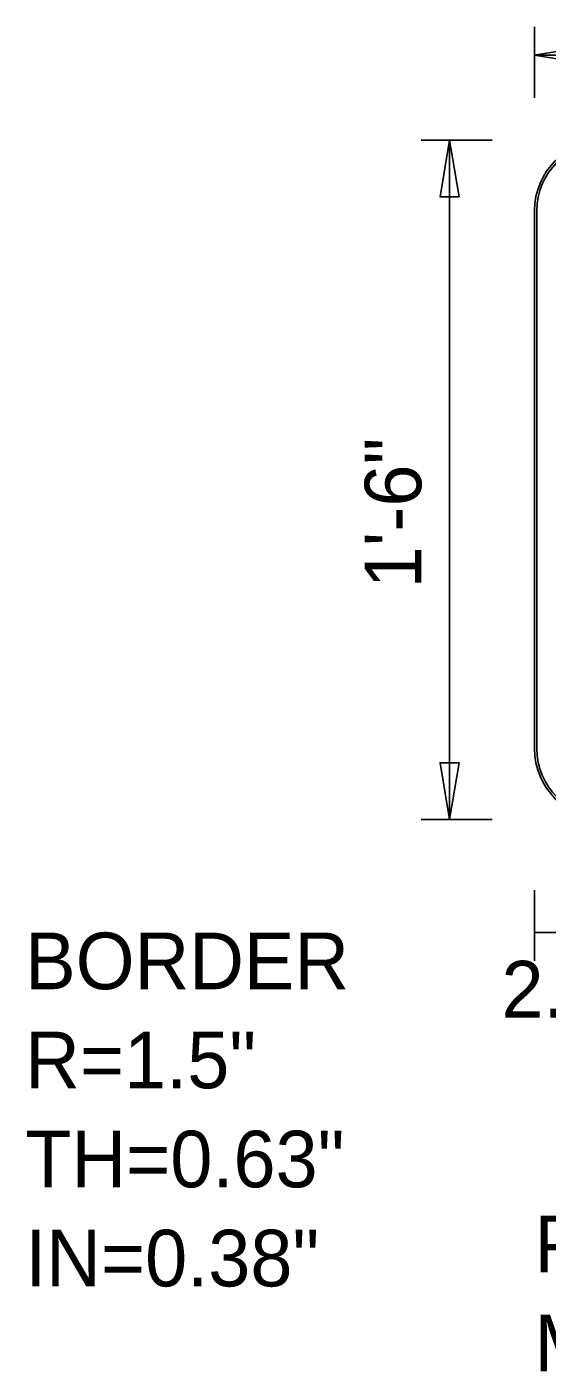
# Model space of a CAD drawing. Extents: x 1788.1 to 1851.2, y 237.2 to 283.4.
# Drawn here: x 1837.493 to 1838.871, y 249.203 to 252.768 of the extents above; entities that cross this region are included whole.
import ezdxf

# ---------------------------------------------------------------- set-up
doc = ezdxf.new("R2010")
doc.units = 0
for name, color, linetype in [('GSBWFILL', 7, 'Continuous'), ('GSCOLORFILL', 7, 'Continuous'), ('GSDIMS', 7, 'Continuous'), ('GSOUTLINE', 7, 'Continuous')]:
    doc.layers.add(name, color=color, linetype=linetype)

msp = doc.modelspace()

# ---------------------------------------------------------------- linework, layer by layer
at = {"layer": 'GSBWFILL'}
msp.add_line((1838.8379, 252.2802), (1838.8379, 250.8552), dxfattribs=at)
for centre, start, end in [((1839.0254, 252.2802), 90, 180), ((1839.0254, 250.8552), 180, 270)]:
    msp.add_arc(centre, 0.1875, start, end, dxfattribs=at)
at = {"layer": 'GSCOLORFILL'}
for p, q in [((1838.8379, 252.2802), (1838.8379, 250.8552)), ((1838.8379, 252.2802), (1838.8379, 250.8552)), ((1838.8441, 250.8552), (1838.8441, 252.2802))]:
    msp.add_line(p, q, dxfattribs=at)
for centre, radius, start, end in [((1839.0254, 252.2802), 0.1875, 90, 180), ((1839.0254, 252.2802), 0.1875, 90, 180), ((1839.0254, 252.2802), 0.1812, 90, 180), ((1839.0254, 250.8552), 0.1875, 180, 270), ((1839.0254, 250.8552), 0.1875, 180, 270), ((1839.0254, 250.8552), 0.1812, 180, 270)]:
    msp.add_arc(centre, radius, start, end, dxfattribs=at)
at = {"layer": 'GSDIMS'}
for p, q in [((1838.8379, 252.5802), (1838.8379, 252.7677)), ((1838.8379, 252.6927), (1843.6379, 252.6927)), ((1838.8379, 252.5802), (1838.8379, 252.5802)), ((1838.7254, 252.4677), (1838.5379, 252.4677)), ((1838.6129, 250.6677), (1838.6129, 252.4677)), ((1838.7254, 252.4677), (1838.7254, 252.4677)), ((1838.7254, 250.6677), (1838.5379, 250.6677)), ((1838.7254, 250.6677), (1838.7254, 250.6677)), ((1838.8379, 250.4802), (1838.8379, 250.2927)), ((1838.8379, 250.4802), (1838.8379, 250.2927)), ((1838.8379, 250.3677), (1839.0854, 250.3677))]:
    msp.add_line(p, q, dxfattribs=at)
for points in [[(1838.8379, 252.6927), (1838.9879, 252.6677), (1838.9879, 252.7177)], [(1838.6129, 252.4677), (1838.6379, 252.3177), (1838.5879, 252.3177)], [(1838.6129, 250.6677), (1838.6379, 250.8177), (1838.5879, 250.8177)]]:
    msp.add_lwpolyline(points, close=True, dxfattribs=at)
at = {"layer": 'GSOUTLINE'}
msp.add_line((1838.8379, 252.2802), (1838.8379, 250.8552), dxfattribs=at)
for centre, start, end in [((1839.0254, 252.2802), 90, 180), ((1839.0254, 250.8552), 180, 270)]:
    msp.add_arc(centre, 0.1875, start, end, dxfattribs=at)

# ---------------------------------------------------------------- texts
at = {"layer": 'GSDIMS'}
msp.add_text('1\'-6"', height=0.15, rotation=90, dxfattribs=at).set_placement((1838.5379, 251.2799))
for s, p in [('BORDER', (1837.4884, 250.2177)), ('2.5"', (1838.7503, 250.1427)), ('R=1.5"', (1837.4884, 249.9552)), ('TH=0.63"', (1837.4884, 249.6927)), ('Panel Style: Traffic Control.ssi', (1838.8379, 249.4677)), ('IN=0.38"', (1837.4884, 249.4302)), ('M.U.T.C.D.:: 2009 Edition', (1838.8379, 249.2052))]:
    msp.add_text(s, height=0.15, dxfattribs=at).set_placement(p)

doc.saveas('drawing.dxf')
